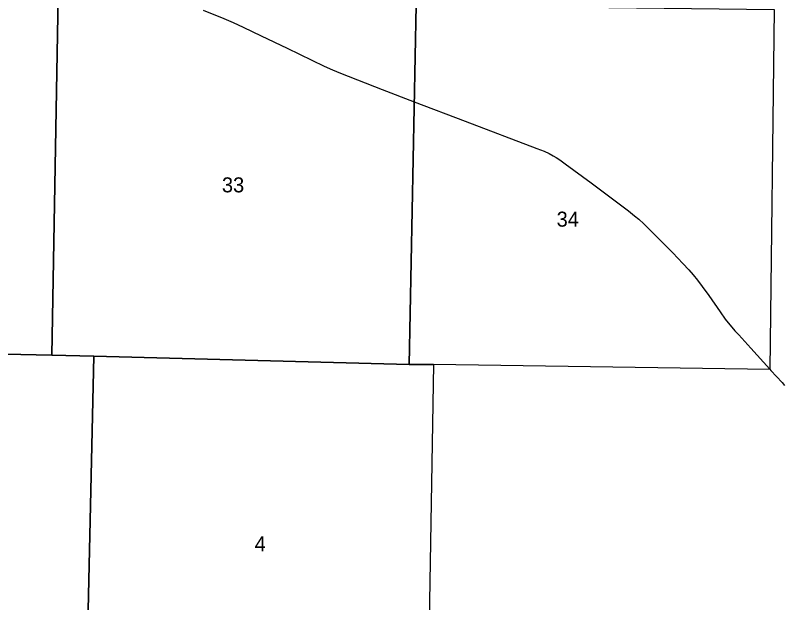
# Model space of a CAD drawing. Extents: x 1587405 to 1714697, y 1028970 to 1155083.
# Drawn here: x 1692632 to 1703984, y 1087753 to 1096415 of the extents above; entities that cross this region are included whole.
import ezdxf

# ---------------------------------------------------------------- set-up
doc = ezdxf.new("R2010")
doc.units = 0
for name, color, linetype in [('GM_X_Section', 7, 'Continuous'), ('GM_X_Section_Text', 7, 'Continuous'), ('GM_X_State_Location', 7, 'Continuous'), ('GM_X_State_Route', 7, 'Continuous')]:
    doc.layers.add(name, color=color, linetype=linetype)

msp = doc.modelspace()

# ---------------------------------------------------------------- linework, layer by layer
at = {"layer": 'GM_X_Section'}
for points in [[(1693264, 1096696), (1693172, 1091402), (1688816, 1091499), (1687836, 1091520), (1687986, 1096826)], [(1698546, 1096565), (1698444, 1091265), (1693788, 1091391), (1693172, 1091402), (1693264, 1096696)], [(1703829, 1096500), (1703766, 1091193), (1698802, 1091266), (1698444, 1091265), (1698546, 1096565)], [(1688816, 1091499), (1693172, 1091402), (1693788, 1091391), (1693674, 1086101), (1688736, 1086256)], [(1698444, 1091265), (1698802, 1091266), (1698714, 1086017), (1693674, 1086101), (1693788, 1091391)]]:
    msp.add_lwpolyline(points, close=True, dxfattribs=at)
at = {"layer": 'GM_X_State_Route'}
msp.add_lwpolyline([(1695404, 1096492), (1695708, 1096369), (1695844, 1096311), (1695993, 1096243), (1696260, 1096115), (1696644, 1095930), (1697191, 1095666), (1697310, 1095612), (1697431, 1095562), (1698043, 1095324), (1698518, 1095141), (1699268, 1094854), (1700327, 1094452), (1700434, 1094411), (1700509, 1094377), (1700567, 1094346), (1700610, 1094321), (1700665, 1094285), (1700746, 1094228), (1701127, 1093944), (1701484, 1093681), (1701680, 1093532), (1701770, 1093460), (1701832, 1093407), (1701905, 1093340), (1702044, 1093201), (1702334, 1092911), (1702482, 1092757), (1702570, 1092660), (1702635, 1092586), (1702697, 1092509), (1702767, 1092417), (1702863, 1092284), (1703031, 1092042), (1703108, 1091934), (1703251, 1091764), (1703309, 1091704), (1703483, 1091507), (1703763, 1091198), (1703780, 1091179), (1703946, 1090998), (1703984, 1090955)], dxfattribs=at)

# ---------------------------------------------------------------- texts
at = {"layer": 'GM_X_Section_Text'}
for s, p in [('33', (1695680, 1093805)), ('34', (1700619, 1093299)), ('4', (1696162, 1088509))]:
    msp.add_text(s, height=221, rotation=0, dxfattribs=at).set_placement(p)
at = {"layer": 'GM_X_State_Location'}
for s in ['s', 'r']:
    msp.add_text(s, height=1, dxfattribs=at).set_placement((1702631, 1092475))
msp.add_text('568', height=1, rotation=0, dxfattribs=at).set_placement((1702278, 1092402))

doc.saveas('drawing.dxf')
